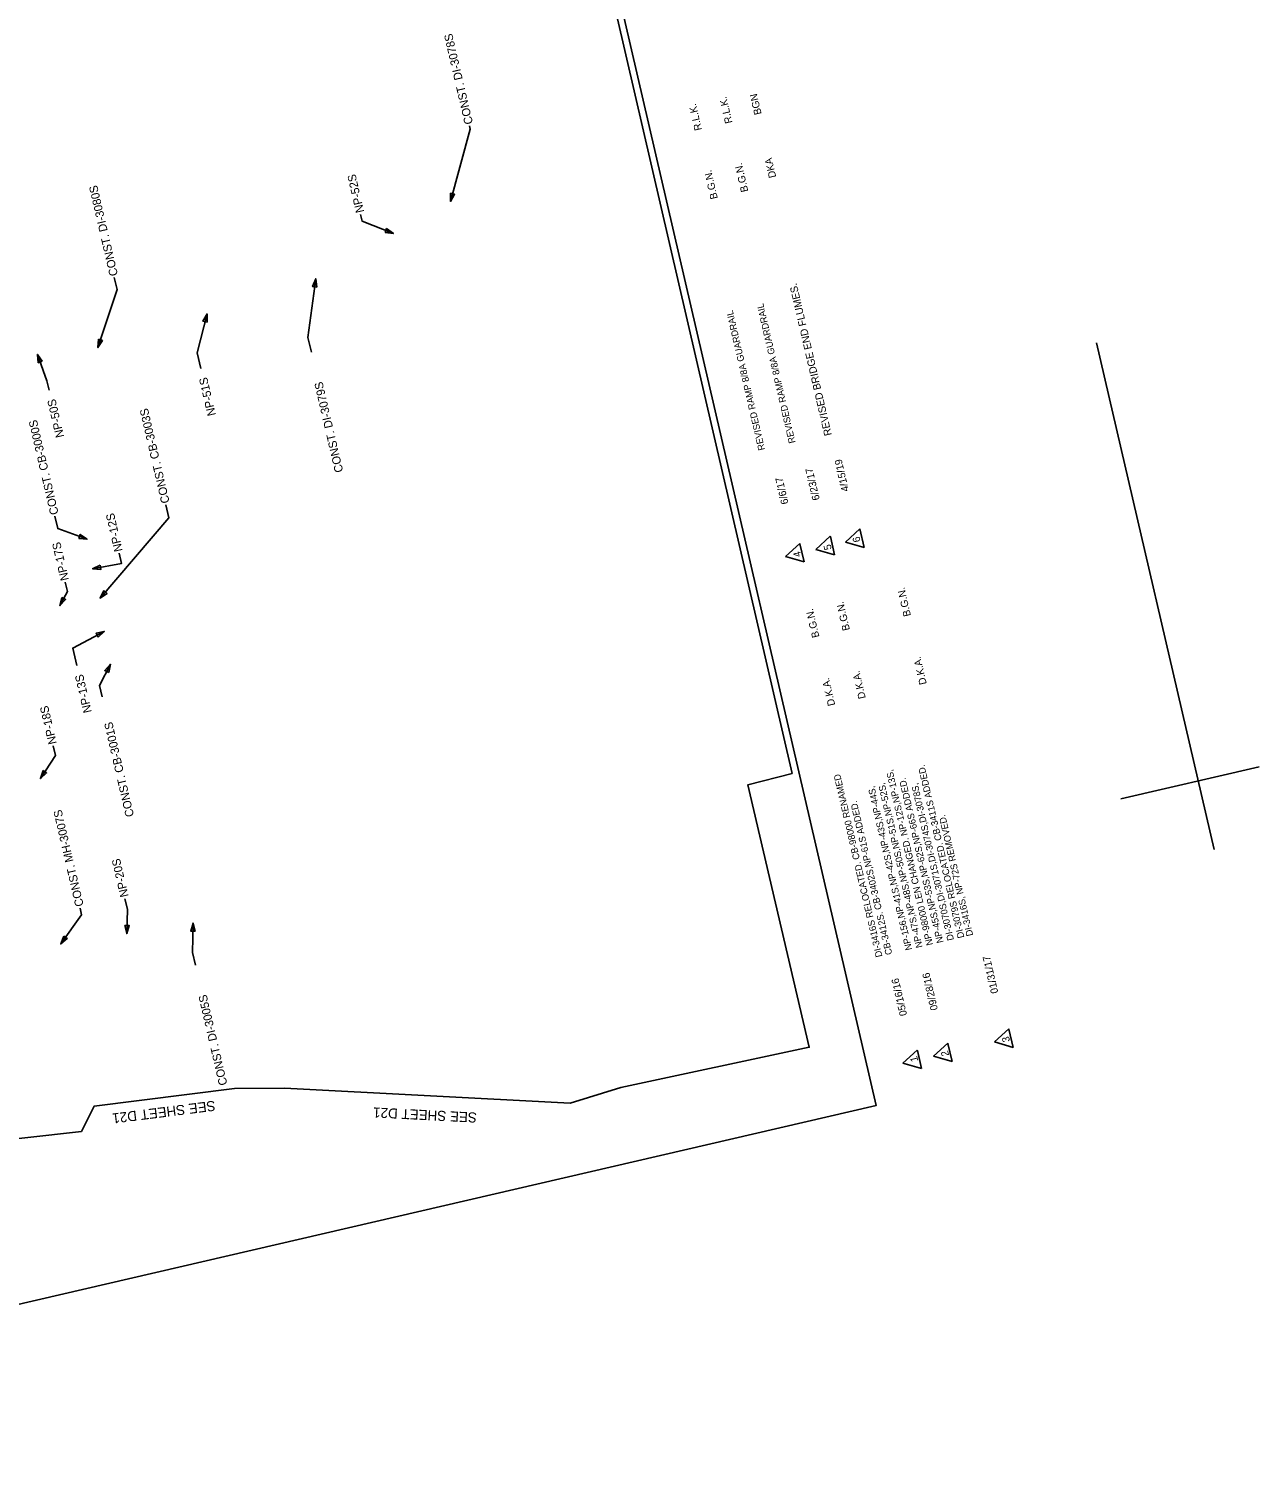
# Model space of a CAD drawing. Extents: x 1611522 to 1613146, y 1089913 to 1091760.
# Drawn here: x 1612412 to 1613146, y 1089913 to 1090772 of the extents above; entities that cross this region are included whole.
import ezdxf

# ---------------------------------------------------------------- set-up
doc = ezdxf.new("R2010")
doc.units = 0
for name, color, linetype in [('Level 2', 7, 'Continuous'), ('Plan_Clip', 7, 'Continuous'), ('RD_SHT_MatchLine', 7, 'Continuous'), ('RD_SHT_TX', 7, 'Continuous'), ('RD_TX_Drainage', 7, 'Continuous')]:
    doc.layers.add(name, color=color, linetype=linetype)

msp = doc.modelspace()

# ---------------------------------------------------------------- linework, layer by layer
at = {"layer": 'Level 2'}
msp.add_lwpolyline([(1611985.8, 1089912.73), (1611607.62, 1091544.48), (1612539.42, 1091760.44), (1612917.6, 1090128.69)], close=True, dxfattribs=at)
at = {"layer": 'Plan_Clip'}
msp.add_lwpolyline([(1611661.84, 1091320.85), (1611963.63, 1090019.87), (1611998.55, 1090017.48), (1612099.34, 1090047.25), (1612244.44, 1090086.86), (1612241.08, 1090099.16), (1612241.08, 1090099.16), (1612309.86, 1090110.54), (1612311.21, 1090098.49), (1612443.02, 1090113.24), (1612450.72, 1090128.31), (1612534.46, 1090138.91), (1612564.39, 1090139.03), (1612734.94, 1090130.1), (1612765.21, 1090139.4), (1612877.73, 1090163.44), (1612841.1, 1090320.18), (1612867.45, 1090326.93), (1612548.32, 1091705.46)], dxfattribs=at)
msp.add_lwpolyline([(1611661.84, 1091320.85), (1611963.63, 1090019.87), (1611998.55, 1090017.48), (1612099.34, 1090047.25), (1612244.44, 1090086.86), (1612241.08, 1090099.16), (1612241.08, 1090099.16), (1612309.86, 1090110.54), (1612311.21, 1090098.49), (1612443.02, 1090113.24), (1612450.72, 1090128.31), (1612534.46, 1090138.91), (1612564.39, 1090139.03), (1612734.94, 1090130.1), (1612765.21, 1090139.4), (1612877.73, 1090163.44), (1612841.1, 1090320.18), (1612867.45, 1090326.93), (1612548.32, 1091705.46)], dxfattribs=at)
msp.add_lwpolyline([(1611661.84, 1091320.85), (1611963.63, 1090019.87), (1611998.55, 1090017.48), (1612099.34, 1090047.25), (1612244.44, 1090086.86), (1612241.08, 1090099.16), (1612241.08, 1090099.16), (1612309.86, 1090110.54), (1612311.21, 1090098.49), (1612443.02, 1090113.24), (1612450.72, 1090128.31), (1612534.46, 1090138.91), (1612564.39, 1090139.03), (1612734.94, 1090130.1), (1612765.21, 1090139.4), (1612877.73, 1090163.44), (1612841.1, 1090320.18), (1612867.45, 1090326.93), (1612548.32, 1091705.46)], dxfattribs=at)
msp.add_lwpolyline([(1611661.84, 1091320.85), (1611963.63, 1090019.87), (1611998.55, 1090017.48), (1612099.34, 1090047.25), (1612244.44, 1090086.86), (1612241.08, 1090099.16), (1612241.08, 1090099.16), (1612309.86, 1090110.54), (1612311.21, 1090098.49), (1612443.02, 1090113.24), (1612450.72, 1090128.31), (1612534.46, 1090138.91), (1612564.39, 1090139.03), (1612734.94, 1090130.1), (1612765.21, 1090139.4), (1612877.73, 1090163.44), (1612841.1, 1090320.18), (1612867.45, 1090326.93), (1612548.32, 1091705.46)], dxfattribs=at)
msp.add_lwpolyline([(1611661.84, 1091320.85), (1611963.63, 1090019.87), (1611998.55, 1090017.48), (1612099.34, 1090047.25), (1612244.44, 1090086.86), (1612241.08, 1090099.16), (1612241.08, 1090099.16), (1612309.86, 1090110.54), (1612311.21, 1090098.49), (1612443.02, 1090113.24), (1612450.72, 1090128.31), (1612534.46, 1090138.91), (1612564.39, 1090139.03), (1612734.94, 1090130.1), (1612765.21, 1090139.4), (1612877.73, 1090163.44), (1612841.1, 1090320.18), (1612867.45, 1090326.93), (1612548.32, 1091705.46)], dxfattribs=at)
msp.add_lwpolyline([(1611661.84, 1091320.85), (1611963.63, 1090019.87), (1611998.55, 1090017.48), (1612099.34, 1090047.25), (1612244.44, 1090086.86), (1612241.08, 1090099.16), (1612241.08, 1090099.16), (1612309.86, 1090110.54), (1612311.21, 1090098.49), (1612443.02, 1090113.24), (1612450.72, 1090128.31), (1612534.46, 1090138.91), (1612564.39, 1090139.03), (1612734.94, 1090130.1), (1612765.21, 1090139.4), (1612877.73, 1090163.44), (1612841.1, 1090320.18), (1612867.45, 1090326.93), (1612548.32, 1091705.46)], dxfattribs=at)
msp.add_lwpolyline([(1611661.84, 1091320.85), (1611963.63, 1090019.87), (1611998.55, 1090017.48), (1612099.34, 1090047.25), (1612244.44, 1090086.86), (1612241.08, 1090099.16), (1612241.08, 1090099.16), (1612309.86, 1090110.54), (1612311.21, 1090098.49), (1612443.02, 1090113.24), (1612450.72, 1090128.31), (1612534.46, 1090138.91), (1612564.39, 1090139.03), (1612734.94, 1090130.1), (1612765.21, 1090139.4), (1612877.73, 1090163.44), (1612841.1, 1090320.18), (1612867.45, 1090326.93), (1612548.32, 1091705.46)], dxfattribs=at)
at = {"layer": 'RD_SHT_TX'}
for p, q in [((1613049.33, 1090584.09), (1613119.46, 1090281.51)), ((1612890.23, 1090468.54), (1612881.69, 1090460.75)), ((1612890.34, 1090468.35), (1612890.23, 1090468.54)), ((1612892.86, 1090457.5), (1612890.34, 1090468.35)), ((1612907.93, 1090472.91), (1612899.32, 1090465.08)), ((1612910.5, 1090461.82), (1612907.93, 1090472.91)), ((1612872.01, 1090464.32), (1612863.47, 1090456.53)), ((1612872.13, 1090464.13), (1612872.01, 1090464.32)), ((1612874.64, 1090453.28), (1612872.13, 1090464.13)), ((1612881.69, 1090460.75), (1612892.86, 1090457.5)), ((1612899.32, 1090465.08), (1612910.5, 1090461.82)), ((1612863.47, 1090456.53), (1612874.64, 1090453.28)), ((1613146.42, 1090330.87), (1613063.67, 1090311.7)), ((1612996.79, 1090174.4), (1612988.25, 1090166.62)), ((1612996.9, 1090174.22), (1612996.79, 1090174.4)), ((1612999.42, 1090163.36), (1612996.9, 1090174.22)), ((1612942.14, 1090161.74), (1612933.6, 1090153.95)), ((1612942.25, 1090161.55), (1612942.14, 1090161.74)), ((1612944.77, 1090150.7), (1612942.25, 1090161.55)), ((1612960.36, 1090165.96), (1612951.81, 1090158.17)), ((1612960.47, 1090165.77), (1612960.36, 1090165.96)), ((1612962.99, 1090154.92), (1612960.47, 1090165.77)), ((1612988.25, 1090166.62), (1612999.42, 1090163.36)), ((1612933.6, 1090153.95), (1612944.77, 1090150.7)), ((1612951.81, 1090158.17), (1612962.99, 1090154.92))]:
    msp.add_line(p, q, dxfattribs=at)
at = {"layer": 'RD_TX_Drainage'}
for points in [[(1612674.7, 1090713.55), (1612675.14, 1090711.64), (1612663.4, 1090668.46)], [(1612609.74, 1090660.76), (1612610.68, 1090656.72), (1612629.33, 1090649.3)], [(1612462.68, 1090623.01), (1612464.31, 1090615.97), (1612452.88, 1090581.22)], [(1612580.39, 1090578.38), (1612578.34, 1090587.23), (1612582.97, 1090622.28)], [(1612514.39, 1090568.67), (1612512.23, 1090577.98), (1612518.06, 1090601.35)], [(1612423.78, 1090555.7), (1612422.44, 1090561.46), (1612416.81, 1090577.17)], [(1612493.55, 1090487.29), (1612495.34, 1090479.53), (1612454.2, 1090431.65)], [(1612427.25, 1090480.47), (1612428.95, 1090473.13), (1612446.41, 1090466.82)], [(1612465.5, 1090458.41), (1612466.92, 1090452.29), (1612449.71, 1090449.13)], [(1612433.41, 1090441.12), (1612434.68, 1090435.65), (1612430.18, 1090427.17)], [(1612440.28, 1090391.34), (1612437.85, 1090401.84), (1612456.69, 1090411.77)], [(1612455.46, 1090372.74), (1612453.91, 1090379.4), (1612460.36, 1090392.11)], [(1612426.14, 1090343.4), (1612427.48, 1090337.64), (1612418.56, 1090323.93)], [(1612442.25, 1090246.57), (1612443.17, 1090242.58), (1612430.74, 1090225.14)], [(1612469.04, 1090252.18), (1612470.51, 1090245.85), (1612470.16, 1090231.36)], [(1612511.2, 1090212.43), (1612509.43, 1090220.04), (1612509.76, 1090237.61)]]:
    msp.add_lwpolyline(points, dxfattribs=at)
for points in [[(1612663.42, 1090673.46), (1612663.4, 1090668.46), (1612665.92, 1090672.78)], [(1612624.37, 1090649.88), (1612629.33, 1090649.3), (1612625.32, 1090652.29)], [(1612583.62, 1090617.32), (1612582.97, 1090622.28), (1612581.05, 1090617.66)], [(1612518.15, 1090596.35), (1612518.06, 1090601.35), (1612515.64, 1090596.98)], [(1612453.16, 1090586.21), (1612452.88, 1090581.22), (1612455.62, 1090585.41)], [(1612419.66, 1090573.06), (1612416.81, 1090577.17), (1612417.22, 1090572.19)], [(1612441.43, 1090467.25), (1612446.41, 1090466.82), (1612442.31, 1090469.68)], [(1612454.23, 1090451.27), (1612449.71, 1090449.13), (1612454.7, 1090448.73)], [(1612456.36, 1090436.16), (1612454.2, 1090431.65), (1612458.33, 1090434.47)], [(1612431.3, 1090432.04), (1612430.18, 1090427.17), (1612433.59, 1090430.83)], [(1612453.02, 1090408.38), (1612456.69, 1090411.77), (1612451.81, 1090410.67)], [(1612459.33, 1090387.22), (1612460.36, 1090392.11), (1612457.02, 1090388.39)], [(1612420.11, 1090328.69), (1612418.56, 1090323.93), (1612422.28, 1090327.27)], [(1612468.98, 1090236.22), (1612470.16, 1090231.36), (1612471.57, 1090236.16)], [(1612510.96, 1090232.76), (1612509.76, 1090237.61), (1612508.37, 1090232.81)], [(1612432.49, 1090229.83), (1612430.74, 1090225.14), (1612434.59, 1090228.32)]]:
    msp.add_lwpolyline(points, close=True, dxfattribs=at)

# ---------------------------------------------------------------- texts
at = {"layer": 'RD_SHT_MatchLine'}
for rotation, p in [(187.21882, (1612522.66, 1090131.63)), (177.09639, (1612679.31, 1090124.43))]:
    msp.add_text('SEE SHEET D21', height=6, rotation=rotation, dxfattribs=at).set_placement(p)
at = {"layer": 'RD_SHT_TX'}
for s, height, rotation, p in [('R.L.K.', 4.4, 103.04878, (1612813.63, 1090711.3)), ('R.L.K.', 4.4, 103.04878, (1612831.84, 1090715.52)), ('BGN', 4.4, 103.05041, (1612849.27, 1090720.73)), ('B.G.N.', 4.4, 103.04878, (1612841.33, 1090674.57)), ('DKA', 4.4, 103.05041, (1612858, 1090683.05)), ('B.G.N.', 4.4, 103.04878, (1612823.12, 1090670.35)), ('REVISED BRIDGE END FLUMES.', 4.5, 103.05041, (1612891.19, 1090529.08)), ('REVISED RAMP 8/8A GUARDRAIL', 4, 103.04878, (1612869.52, 1090524.53)), ('REVISED RAMP 8/8A GUARDRAIL', 4, 103.04878, (1612851.31, 1090520.31)), ('4/15/19', 4.4, 103.05041, (1612901.41, 1090495.78)), ('6/6/17', 4.4, 103.04878, (1612865.34, 1090488.18)), ('6/23/17', 4.4, 103.04878, (1612883.99, 1090490.54)), ('6', 4.4, 103.05041, (1612908.42, 1090465.53)), ('4', 4.4, 103.04878, (1612872.93, 1090456.68)), ('5', 4.4, 103.04878, (1612891.15, 1090460.9)), ('B.G.N.', 4.4, 103.04878, (1612938.45, 1090421.18)), ('B.G.N.', 4.4, 103.04878, (1612883.8, 1090408.51)), ('B.G.N.', 4.4, 103.04878, (1612902.02, 1090412.73)), ('D.K.A.', 4.4, 103.04878, (1612947.89, 1090380.47)), ('D.K.A.', 4.4, 103.04878, (1612893.24, 1090367.8)), ('D.K.A.', 4.4, 103.04878, (1612911.45, 1090372.02)), ('DI-3079S RELOCATED. CB-3411S ADDED.', 4, 103.04878, (1612970.36, 1090229.07)), ('DI-3416S RELOCATED. CB-98000 RENAMED', 4, 103.04878, (1612921.43, 1090217.73)), ('NP-98000 LEN CHANGED. NP-12S,NP-13S,', 4, 103.04878, (1612951.66, 1090224.74)), ('NP-45S,NP-53S,NP-62S,NP-66S ADDED.', 4, 103.04878, (1612957.89, 1090226.18)), ('NP-156,NP-41S,NP-42S,NP-43S,NP-44S,', 4, 103.04878, (1612939.19, 1090221.85)), ('NP-47S,NP-48S,NP-50S,NP-51S,NP-52S,', 4, 103.04878, (1612945.42, 1090223.29)), ('DI-3070S,DI-3071S,DI-3074S,DI-3078S,', 4, 103.04878, (1612964.13, 1090227.63)), ('CB-3412S. CB-3402S,NP-61S ADDED.', 4, 103.04878, (1612927.28, 1090219.09)), ('DI-3416S, NP-72S REMOVED.', 4, 103.04878, (1612975.62, 1090230.29)), ('01/31/17', 4.4, 103.04878, (1612990.62, 1090196.1)), ('05/16/16', 4.4, 103.04878, (1612936.13, 1090182.74)), ('09/28/16', 4.4, 103.04878, (1612954.56, 1090186.03)), ('3', 4.4, 103.04878, (1612997.64, 1090167.06)), ('2', 4.4, 103.04878, (1612961.21, 1090158.61)), ('1', 4.4, 103.04878, (1612942.77, 1090155.34))]:
    msp.add_text(s, height=height, rotation=rotation, dxfattribs=at).set_placement(p)
at = {"layer": 'RD_TX_Drainage'}
for s, p in [('CONST. DI-3078S', (1612676.91, 1090715.09)), ('NP-52S', (1612611.95, 1090662.3)), ('CONST. DI-3080S', (1612464.89, 1090624.54)), ('NP-51S', (1612523.36, 1090541.03)), ('CONST. DI-3079S', (1612599.44, 1090507.25)), ('NP-50S', (1612432.75, 1090528.05)), ('CONST. CB-3000S', (1612429.46, 1090482)), ('CONST. CB-3003S', (1612495.76, 1090488.83)), ('NP-12S', (1612467.71, 1090459.95)), ('NP-17S', (1612435.62, 1090442.66)), ('NP-13S', (1612449.25, 1090363.7)), ('NP-18S', (1612428.35, 1090344.94)), ('CONST. CB-3001S', (1612474.51, 1090301.61)), ('CONST. MH-3007S', (1612444.46, 1090248.11)), ('NP-20S', (1612471.25, 1090253.72)), ('CONST. DI-3005S', (1612530.25, 1090141.3))]:
    msp.add_text(s, height=5, rotation=103.04878, dxfattribs=at).set_placement(p)

doc.saveas('drawing.dxf')
